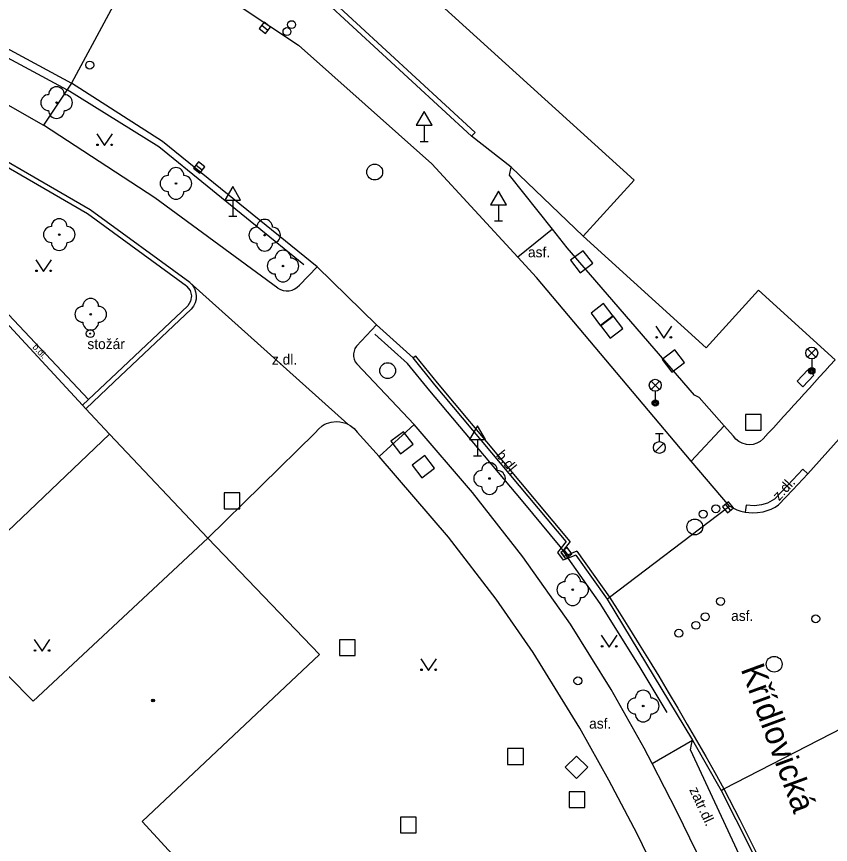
# Model space of a CAD drawing. Extents: x -598932 to -598196, y -1162207 to -1161504.
# Drawn here: x -598749.6 to -598698.1, y -1161610 to -1161557.6 of the extents above; entities that cross this region are included whole.
import ezdxf

# ---------------------------------------------------------------- set-up
doc = ezdxf.new("R2010")
doc.units = 0
for name, color, linetype in [('Level 22', 7, 'Continuous'), ('Level 24', 7, 'Continuous'), ('Level 25', 7, 'Continuous'), ('Level 26', 7, 'Continuous'), ('Level 27', 7, 'Continuous'), ('Level 28', 7, 'Continuous'), ('Level 33', 7, 'Continuous'), ('Level 34', 7, 'Continuous'), ('Level 36', 7, 'Continuous'), ('Level 39', 7, 'Continuous'), ('specificka linie pasportu komunikaci', 7, 'Continuous'), ('TM - budovy zdene_ betonove - VP', 7, 'Continuous'), ('TM - chodniky - VP', 7, 'Continuous'), ('TM - komunikace - VP', 7, 'Continuous'), ('TM - plot dreveny_ kovovy - VP', 7, 'Continuous'), ('TM - plot zdeny_ ohradni zed - VP', 7, 'Continuous'), ('TM - podezdivka plotu - VP', 7, 'Continuous'), ('TM - pomocna konstrukcna linie', 7, 'Continuous'), ('TM - popis povrchu', 7, 'Continuous'), ('TM - poznamka', 7, 'Continuous'), ('TM - rozhrani mezi zpev. plochami mezi sebou - VP', 7, 'Continuous'), ('TM - rozhrani ploch obecne - VP', 7, 'Continuous'), ('TM - vjezd na pozemek', 7, 'Continuous'), ('TM - zabradli - VP', 7, 'Continuous'), ('ulice', 7, 'Continuous')]:
    doc.layers.add(name, color=color, linetype=linetype)

msp = doc.modelspace()

# ---------------------------------------------------------------- linework, layer by layer
at = {"layer": 'Level 22'}
for centre in [(-598747.06, -1161563.09), (-598739.51, -1161568.2), (-598746.89, -1161571.43), (-598733.9, -1161571.47), (-598732.74, -1161573.42), (-598744.9, -1161576.47), (-598719.68, -1161586.85), (-598714.42, -1161593.88), (-598709.96, -1161601.23)]:
    msp.add_circle(centre, 0.05, dxfattribs=at)
for centre, start, end in [((-598747.06, -1161562.59), 0, 180), ((-598747.56, -1161563.09), 90, 270), ((-598746.56, -1161563.09), 270, 90), ((-598747.06, -1161563.59), 180, 0), ((-598739.51, -1161567.7), 0, 180), ((-598740.01, -1161568.2), 90, 270), ((-598739.01, -1161568.2), 270, 90), ((-598739.51, -1161568.7), 180, 0), ((-598746.89, -1161570.93), 0, 180), ((-598733.9, -1161570.97), 0, 180), ((-598747.39, -1161571.43), 90, 270), ((-598746.39, -1161571.43), 270, 90), ((-598734.4, -1161571.47), 90, 270), ((-598733.4, -1161571.47), 270, 90), ((-598746.89, -1161571.93), 180, 0), ((-598733.9, -1161571.97), 180, 0), ((-598732.74, -1161572.92), 0, 180), ((-598733.24, -1161573.42), 90, 270), ((-598732.24, -1161573.42), 270, 90), ((-598732.74, -1161573.92), 180, 0), ((-598744.9, -1161575.97), 0, 180), ((-598745.4, -1161576.47), 90, 270), ((-598744.4, -1161576.47), 270, 90), ((-598744.9, -1161576.97), 180, 0), ((-598719.68, -1161586.35), 0, 180), ((-598720.18, -1161586.85), 90, 270), ((-598719.18, -1161586.85), 270, 90), ((-598719.68, -1161587.35), 180, 0), ((-598714.42, -1161593.38), 0, 180), ((-598714.92, -1161593.88), 90, 270), ((-598713.92, -1161593.88), 270, 90), ((-598714.42, -1161594.38), 180, 0), ((-598709.96, -1161600.73), 0, 180), ((-598710.46, -1161601.23), 90, 270), ((-598709.46, -1161601.23), 270, 90), ((-598709.96, -1161601.73), 180, 0)]:
    msp.add_arc(centre, 0.5, start, end, dxfattribs=at)
at = {"layer": 'Level 24'}
msp.add_lwpolyline([(-598699.859, -1161581.046), (-598699.176, -1161580.315), (-598699.541, -1161579.974), (-598700.224, -1161580.705)], close=True, dxfattribs=at)
at = {"layer": 'Level 25'}
for radius in [0.25, 0.0303]:
    msp.add_circle((-598744.93, -1161577.69), radius, dxfattribs=at)
at = {"layer": 'Level 26'}
for points in [[(-598714.551, -1161573.058), (-598713.942, -1161573.851), (-598713.149, -1161573.242), (-598713.758, -1161572.449)], [(-598713.261, -1161576.398), (-598712.652, -1161577.191), (-598711.859, -1161576.582), (-598712.468, -1161575.789)], [(-598712.661, -1161577.178), (-598712.052, -1161577.971), (-598711.259, -1161577.362), (-598711.868, -1161576.569)], [(-598708.761, -1161579.328), (-598708.152, -1161580.121), (-598707.359, -1161579.512), (-598707.968, -1161578.719)], [(-598703.5, -1161583.8), (-598702.5, -1161583.8), (-598702.5, -1161582.8), (-598703.5, -1161582.8)], [(-598725.911, -1161584.498), (-598725.302, -1161585.291), (-598724.509, -1161584.682), (-598725.118, -1161583.889)], [(-598724.571, -1161586.008), (-598723.962, -1161586.801), (-598723.169, -1161586.192), (-598723.778, -1161585.399)], [(-598736.47, -1161588.76), (-598735.47, -1161588.76), (-598735.47, -1161587.76), (-598736.47, -1161587.76)], [(-598729.17, -1161598.04), (-598728.17, -1161598.04), (-598728.17, -1161597.04), (-598729.17, -1161597.04)], [(-598718.54, -1161604.92), (-598717.54, -1161604.92), (-598717.54, -1161603.92), (-598718.54, -1161603.92)], [(-598714.887, -1161605.1), (-598714.18, -1161605.807), (-598713.473, -1161605.1), (-598714.18, -1161604.393)], [(-598714.65, -1161607.65), (-598713.65, -1161607.65), (-598713.65, -1161606.65), (-598714.65, -1161606.65)], [(-598725.31, -1161609.25), (-598724.31, -1161609.25), (-598724.31, -1161608.25), (-598725.31, -1161608.25)]]:
    msp.add_lwpolyline(points, close=True, dxfattribs=at)
at = {"layer": 'Level 27'}
for p, q in [((-598734.084, -1161558.203), (-598733.696, -1161558.517)), ((-598738.234, -1161567.033), (-598737.846, -1161567.347)), ((-598704.438, -1161588.86), (-598704.762, -1161588.48)), ((-598714.97, -1161591.37), (-598714.67, -1161591.77))]:
    msp.add_line(p, q, dxfattribs=at)
for points in [[(-598734.242, -1161558.397), (-598733.853, -1161558.712), (-598733.538, -1161558.323), (-598733.927, -1161558.008)], [(-598738.392, -1161567.227), (-598738.003, -1161567.542), (-598737.688, -1161567.153), (-598738.077, -1161566.838)], [(-598704.248, -1161588.698), (-598704.572, -1161588.318), (-598704.952, -1161588.642), (-598704.628, -1161589.022)], [(-598715.17, -1161591.52), (-598714.87, -1161591.92), (-598714.47, -1161591.62), (-598714.77, -1161591.22)]]:
    msp.add_lwpolyline(points, close=True, dxfattribs=at)
for centre in [(-598726.94, -1161567.48), (-598726.12, -1161580.03), (-598706.7, -1161589.91), (-598701.68, -1161598.59)]:
    msp.add_circle(centre, 0.5, dxfattribs=at)
at = {"layer": 'Level 28'}
for p, q in [((-598709.19, -1161584.015), (-598708.69, -1161584.015)), ((-598708.94, -1161584.515), (-598708.94, -1161584.015)), ((-598709.198, -1161585.162), (-598708.668, -1161584.632))]:
    msp.add_line(p, q, dxfattribs=at)
for centre, radius in [((-598732.2, -1161558.16), 0.25), ((-598732.49, -1161558.6), 0.25), ((-598744.96, -1161560.72), 0.25), ((-598708.94, -1161584.89), 0.375), ((-598706.17, -1161589.1), 0.25), ((-598705.37, -1161588.76), 0.25), ((-598705.07, -1161594.62), 0.25), ((-598706.04, -1161595.59), 0.25), ((-598699.05, -1161595.72), 0.25), ((-598706.63, -1161596.13), 0.25), ((-598707.71, -1161596.63), 0.25), ((-598714.09, -1161599.64), 0.25)]:
    msp.add_circle(centre, radius, dxfattribs=at)
at = {"layer": 'Level 33'}
for p, q in [((-598699.565, -1161579.18), (-598699.035, -1161578.65)), ((-598699.565, -1161578.65), (-598699.035, -1161579.18)), ((-598699.3, -1161579.29), (-598699.3, -1161580.04)), ((-598709.465, -1161581.22), (-598708.935, -1161580.69)), ((-598709.465, -1161580.69), (-598708.935, -1161581.22)), ((-598709.2, -1161581.33), (-598709.2, -1161582.08))]:
    msp.add_line(p, q, dxfattribs=at)
for centre, radius in [((-598699.3, -1161578.915), 0.375), ((-598699.3, -1161580.04), 0.2), ((-598699.3, -1161580.04), 0.145), ((-598699.3, -1161580.04), 0.0876), ((-598709.2, -1161580.955), 0.375), ((-598709.2, -1161582.08), 0.2), ((-598709.2, -1161582.08), 0.145), ((-598709.2, -1161582.08), 0.0876)]:
    msp.add_circle(centre, radius, dxfattribs=at)
at = {"layer": 'Level 34'}
for p, q in [((-598723.81, -1161564.522), (-598723.81, -1161565.54)), ((-598724.06, -1161565.54), (-598723.56, -1161565.54)), ((-598735.92, -1161569.252), (-598735.92, -1161570.27)), ((-598719.11, -1161569.552), (-598719.11, -1161570.57)), ((-598736.17, -1161570.27), (-598735.67, -1161570.27)), ((-598719.36, -1161570.57), (-598718.86, -1161570.57)), ((-598720.44, -1161584.392), (-598720.44, -1161585.41)), ((-598720.69, -1161585.41), (-598720.19, -1161585.41))]:
    msp.add_line(p, q, dxfattribs=at)
for points in [[(-598724.31, -1161564.522), (-598723.31, -1161564.522), (-598723.81, -1161563.656)], [(-598736.42, -1161569.252), (-598735.42, -1161569.252), (-598735.92, -1161568.386)], [(-598719.61, -1161569.552), (-598718.61, -1161569.552), (-598719.11, -1161568.686)], [(-598720.94, -1161584.392), (-598719.94, -1161584.392), (-598720.44, -1161583.526)]]:
    msp.add_lwpolyline(points, close=True, dxfattribs=at)
at = {"layer": 'Level 36'}
for points in [[(-598744.52, -1161565.06), (-598744.02, -1161565.81), (-598743.52, -1161565.06)], [(-598748.38, -1161573.02), (-598747.88, -1161573.77), (-598747.38, -1161573.02)], [(-598709.16, -1161577.22), (-598708.66, -1161577.97), (-598708.16, -1161577.22)], [(-598712.61, -1161596.76), (-598712.11, -1161597.51), (-598711.61, -1161596.76)], [(-598748.48, -1161597.02), (-598747.98, -1161597.77), (-598747.48, -1161597.02)], [(-598724.03, -1161598.24), (-598723.53, -1161598.99), (-598723.03, -1161598.24)]]:
    msp.add_lwpolyline(points, dxfattribs=at)
for centre in [(-598744.47, -1161565.76), (-598743.571, -1161565.76), (-598748.33, -1161573.72), (-598747.431, -1161573.72), (-598709.11, -1161577.92), (-598708.211, -1161577.92), (-598748.43, -1161597.72), (-598747.531, -1161597.72), (-598712.56, -1161597.46), (-598711.661, -1161597.46), (-598723.98, -1161598.94), (-598723.081, -1161598.94)]:
    msp.add_circle(centre, 0.05, dxfattribs=at)
at = {"layer": 'Level 39'}
for radius in [0.09, 0.0398]:
    msp.add_circle((-598740.96, -1161600.88), radius, dxfattribs=at)
at = {"layer": 'specificka linie pasportu komunikaci'}
for points in [[(-598738.57, -1161548.92), (-598740.04, -1161550.84), (-598741.44, -1161553.15), (-598746.11, -1161561.87), (-598747.89, -1161564.52)], [(-598715.7, -1161571.08), (-598717.9, -1161572.85)], [(-598728.63, -1161583.42), (-598738.63, -1161574.46)], [(-598712.25, -1161594.47), (-598712.089, -1161594.348), (-598704.66, -1161588.711), (-598704.5, -1161588.59)], [(-598704.86, -1161606.47), (-598696.57, -1161602.2)], [(-598709.4, -1161604.87), (-598706.84, -1161603.38)], [(-598702.18, -1161614.28), (-598702.35, -1161613.92), (-598706.97, -1161604)], [(-598705.04, -1161606.56), (-598704.86, -1161606.47)]]:
    msp.add_lwpolyline(points, dxfattribs=at)
at = {"layer": 'TM - budovy zdene_ betonove - VP'}
for points in [[(-598710.53, -1161568), (-598732.68, -1161547.89)], [(-598713.75, -1161571.54), (-598710.53, -1161568)], [(-598705.99, -1161578.59), (-598713.75, -1161571.54)], [(-598702.67, -1161574.94), (-598705.99, -1161578.59)], [(-598697.83, -1161579.35), (-598702.67, -1161574.94)], [(-598751.1, -1161576.11), (-598745.41, -1161582.22)], [(-598745.41, -1161582.22), (-598745.2, -1161582.44)], [(-598745.2, -1161582.44), (-598743.71, -1161584.04)], [(-598743.71, -1161584.04), (-598754.81, -1161594.61)], [(-598748.53, -1161600.93), (-598737.49, -1161590.63)], [(-598737.49, -1161590.63), (-598730.43, -1161597.98)], [(-598754.81, -1161594.61), (-598748.53, -1161600.93)], [(-598730.43, -1161597.98), (-598741.65, -1161608.53)], [(-598741.65, -1161608.53), (-598734.51, -1161616.31)]]:
    msp.add_lwpolyline(points, dxfattribs=at)
at = {"layer": 'TM - chodniky - VP'}
for points in [[(-598738.63, -1161574.46), (-598744.94, -1161569.87), (-598754.34, -1161564.43), (-598767.98, -1161558.84)], [(-598750.15, -1161563.23), (-598747.89, -1161564.52)], [(-598733.07, -1161574.81), (-598740.85, -1161569.1), (-598747.89, -1161564.52)], [(-598704.85, -1161583.51), (-598706.42, -1161581.72), (-598706.72, -1161581.58), (-598714.76, -1161572.26), (-598715.7, -1161571.08), (-598718.42, -1161567.67), (-598718.31, -1161567.16)], [(-598730.57, -1161573.48), (-598731.7, -1161574.62)], [(-598738.63, -1161574.46), (-598738.47, -1161574.631), (-598738.347, -1161574.83), (-598738.266, -1161575.05), (-598738.23, -1161575.28), (-598738.241, -1161575.515), (-598738.298, -1161575.742), (-598738.399, -1161575.953), (-598738.54, -1161576.14)], [(-598733.07, -1161574.81), (-598732.905, -1161574.903), (-598732.725, -1161574.964), (-598732.537, -1161574.991), (-598732.35, -1161574.98), (-598732.163, -1161574.939), (-598731.99, -1161574.862), (-598731.834, -1161574.755), (-598731.7, -1161574.62)], [(-598745.2, -1161582.44), (-598743.41, -1161580.74), (-598738.54, -1161576.14)], [(-598726.82, -1161577.14), (-598728.1, -1161578.49)], [(-598728.1, -1161578.49), (-598728.189, -1161578.637), (-598728.249, -1161578.798), (-598728.277, -1161578.967), (-598728.28, -1161579.05), (-598728.274, -1161579.139), (-598728.24, -1161579.307), (-598728.174, -1161579.466), (-598728.08, -1161579.61)], [(-598697.83, -1161579.35), (-598698.155, -1161579.707), (-598698.48, -1161580.064), (-598698.805, -1161580.421), (-598699.13, -1161580.779), (-598699.455, -1161581.136), (-598699.78, -1161581.493), (-598700.105, -1161581.85), (-598700.43, -1161582.207), (-598700.755, -1161582.564), (-598701.08, -1161582.921), (-598701.405, -1161583.279), (-598701.73, -1161583.636), (-598702.055, -1161583.993), (-598702.38, -1161584.35), (-598702.563, -1161584.504), (-598702.773, -1161584.619), (-598703.001, -1161584.69), (-598703.239, -1161584.715), (-598703.43, -1161584.7), (-598703.705, -1161584.622), (-598703.916, -1161584.509), (-598704.1, -1161584.356), (-598704.25, -1161584.17)], [(-598724.44, -1161583.44), (-598728.08, -1161579.61)], [(-598730.7, -1161583.96), (-598730.501, -1161583.721), (-598730.26, -1161583.524), (-598730.13, -1161583.44), (-598729.986, -1161583.377), (-598729.689, -1161583.284), (-598729.38, -1161583.25), (-598729.14, -1161583.26), (-598728.771, -1161583.359), (-598728.63, -1161583.42), (-598728.493, -1161583.498), (-598728.246, -1161583.687), (-598728.04, -1161583.92)], [(-598707.83, -1161607.9), (-598709.4, -1161604.87), (-598709.9, -1161603.89), (-598711.99, -1161600.18), (-598714.56, -1161596.06), (-598717.57, -1161591.81), (-598720.76, -1161587.74), (-598724.44, -1161583.44)], [(-598704.25, -1161584.17), (-598704.85, -1161583.51)], [(-598737.49, -1161590.63), (-598730.7, -1161583.96)], [(-598726.65, -1161585.45), (-598728.04, -1161583.92)], [(-598709.66, -1161610.71), (-598710.35, -1161609.3), (-598712.13, -1161605.91), (-598713.96, -1161602.63), (-598716.91, -1161597.84), (-598719.26, -1161594.47), (-598722.28, -1161590.55), (-598726.65, -1161585.45)], [(-598704.92, -1161613.86), (-598707.83, -1161607.9)]]:
    msp.add_lwpolyline(points, dxfattribs=at)
at = {"layer": 'TM - komunikace - VP'}
for points in [[(-598767.84, -1161552.52), (-598762.21, -1161554.38), (-598756.7, -1161556.56), (-598751.33, -1161559.06), (-598746.11, -1161561.87)], [(-598741.44, -1161553.15), (-598739.14, -1161554.55), (-598731.75, -1161559.45), (-598723.33, -1161566.95)], [(-598730.57, -1161573.48), (-598740.36, -1161565.55), (-598746.11, -1161561.87)], [(-598706.92, -1161585.75), (-598716.7, -1161574.15), (-598717.9, -1161572.85), (-598723.33, -1161566.95)], [(-598699.54, -1161586.56), (-598695.23, -1161581.73), (-598681.85, -1161567.08)], [(-598726.82, -1161577.14), (-598730.57, -1161573.48)], [(-598724.51, -1161579.23), (-598726.82, -1161577.14)], [(-598714.83, -1161590.83), (-598723.13, -1161580.93), (-598724.51, -1161579.23)], [(-598704.5, -1161588.59), (-598706.92, -1161585.75)], [(-598703.51, -1161588.97), (-598703.06, -1161589.02), (-598702.735, -1161589.007), (-598702.38, -1161588.95), (-598702.069, -1161588.859), (-598701.86, -1161588.78), (-598701.626, -1161588.656), (-598701.41, -1161588.52), (-598700.49, -1161587.56), (-598699.54, -1161586.56)], [(-598704.5, -1161588.59), (-598704.446, -1161588.617), (-598704.04, -1161588.82), (-598703.795, -1161588.906), (-598703.51, -1161588.97)], [(-598714.83, -1161590.83), (-598715.15, -1161591.23)], [(-598715.15, -1161591.23), (-598715.39, -1161591.53), (-598715.03, -1161592.01)], [(-598714.7, -1161591.88), (-598715.03, -1161592.01)], [(-598714.22, -1161591.69), (-598714.7, -1161591.88)], [(-598714.22, -1161591.69), (-598712.25, -1161594.47), (-598706.84, -1161603.38)], [(-598706.84, -1161603.38), (-598705.04, -1161606.56), (-598703.17, -1161610.24), (-598701.39, -1161613.95)]]:
    msp.add_lwpolyline(points, dxfattribs=at)
at = {"layer": 'TM - plot dreveny_ kovovy - VP'}
msp.add_lwpolyline([(-598720.59, -1161564.97), (-598729.97, -1161556.32), (-598742.56, -1161544.87), (-598747.08, -1161540.69)], dxfattribs=at)
at = {"layer": 'TM - plot zdeny_ ohradni zed - VP'}
for points in [[(-598718.31, -1161567.16), (-598720.81, -1161565.21)], [(-598713.75, -1161571.54), (-598718.31, -1161567.16)]]:
    msp.add_lwpolyline(points, dxfattribs=at)
at = {"layer": 'TM - podezdivka plotu - VP'}
msp.add_lwpolyline([(-598730.19, -1161556.56), (-598720.81, -1161565.21), (-598720.59, -1161564.97)], dxfattribs=at)
at = {"layer": 'TM - pomocna konstrukcna linie'}
msp.add_lwpolyline([(-598724.35, -1161579.11), (-598724.51, -1161579.23)], dxfattribs=at)
at = {"layer": 'TM - rozhrani mezi zpev. plochami mezi sebou - VP'}
for points in [[(-598724.44, -1161583.44), (-598726.65, -1161585.45)], [(-598704.85, -1161583.51), (-598706.92, -1161585.75)], [(-598699.54, -1161586.56), (-598699.86, -1161586.26), (-598700.81, -1161587.26), (-598701.66, -1161588.15), (-598702.1, -1161588.4), (-598702.49, -1161588.52), (-598702.93, -1161588.57), (-598703.44, -1161588.53), (-598703.51, -1161588.97)]]:
    msp.add_lwpolyline(points, dxfattribs=at)
at = {"layer": 'TM - rozhrani ploch obecne - VP'}
for points in [[(-598738.84, -1161574.7), (-598745.1, -1161570.12), (-598754.47, -1161564.7), (-598767.24, -1161559.47)], [(-598738.84, -1161574.7), (-598738.62, -1161574.96), (-598738.53, -1161575.3), (-598738.58, -1161575.64), (-598738.76, -1161575.94)], [(-598751.1, -1161576.11), (-598750.79, -1161575.76), (-598745.03, -1161581.86)], [(-598745.41, -1161582.22), (-598745.03, -1161581.86), (-598743.62, -1161580.52), (-598738.76, -1161575.94)], [(-598714.57, -1161590.83), (-598722.98, -1161580.8), (-598724.35, -1161579.11)], [(-598714.57, -1161590.83), (-598715.03, -1161591.4)], [(-598715.03, -1161591.4), (-598715.14, -1161591.53), (-598714.96, -1161591.77)], [(-598714.15, -1161591.45), (-598714.82, -1161591.71)], [(-598714.15, -1161591.45), (-598712.09, -1161594.35)], [(-598714.82, -1161591.71), (-598714.96, -1161591.77)], [(-598712.09, -1161594.35), (-598711.45, -1161595.35), (-598710.83, -1161596.35), (-598710.21, -1161597.35), (-598709.59, -1161598.35), (-598708.98, -1161599.35), (-598708.38, -1161600.36), (-598707.78, -1161601.37), (-598707.19, -1161602.39), (-598706.6, -1161603.4), (-598706.01, -1161604.42), (-598705.43, -1161605.44), (-598704.86, -1161606.47), (-598703.84, -1161608.43), (-598702.85, -1161610.41), (-598701.89, -1161612.4), (-598700.96, -1161614.41), (-598700.06, -1161616.43), (-598699.2, -1161618.47)], [(-598706.9, -1161603.67), (-598706.84, -1161603.38)], [(-598706.97, -1161604), (-598706.9, -1161603.67)]]:
    msp.add_lwpolyline(points, dxfattribs=at)
at = {"layer": 'TM - vjezd na pozemek'}
msp.add_lwpolyline([(-598737.49, -1161590.63), (-598743.71, -1161584.04)], dxfattribs=at)
at = {"layer": 'TM - zabradli - VP'}
for points in [[(-598762.27, -1161554.9), (-598756.83, -1161557.05), (-598751.53, -1161559.52), (-598746.38, -1161562.29)], [(-598731.43, -1161573.34), (-598740.59, -1161565.88), (-598746.38, -1161562.29)], [(-598715.15, -1161591.23), (-598715.21, -1161591.15), (-598717.56, -1161588.33), (-598722.79, -1161582.1), (-598723.46, -1161581.3), (-598724.86, -1161579.57), (-598726.94, -1161577.72)], [(-598715.03, -1161591.4), (-598715.15, -1161591.23)], [(-598714.82, -1161591.71), (-598715.03, -1161591.4)], [(-598714.7, -1161591.88), (-598714.82, -1161591.71)], [(-598708.45, -1161601.64), (-598710.22, -1161598.7), (-598712.68, -1161594.75), (-598714.7, -1161591.88)]]:
    msp.add_lwpolyline(points, dxfattribs=at)

# ---------------------------------------------------------------- texts
at = {"layer": 'TM - popis povrchu'}
for s, p in [('asf.', (-598717.25, -1161572.87)), ('z.dl.', (-598733.44, -1161579.65)), ('asf.', (-598704.4, -1161595.85)), ('asf.', (-598713.38, -1161602.66))]:
    msp.add_text(s, height=0.65, dxfattribs=at).set_placement(p)
for s, height, rotation, p in [('b.dl.', 0.4, 312.9615, (-598748.61, -1161578.57)), ('b.dl.', 0.65, 309.11, (-598719.3, -1161585.39)), ('z.dl.', 0.65, 47.61, (-598701.37, -1161588.3)), ('zatr.dl.', 0.65, 294.72, (-598707.06, -1161606.52))]:
    msp.add_text(s, height=height, rotation=rotation, dxfattribs=at).set_placement(p)
at = {"layer": 'TM - poznamka'}
msp.add_text('stožár', height=0.65, dxfattribs=at).set_placement((-598745.11, -1161578.67))
at = {"layer": 'ulice'}
msp.add_text('Křídlovická', height=1.5, rotation=290.1814, dxfattribs=at).set_placement((-598703.809, -1161598.894))

doc.saveas('drawing.dxf')
